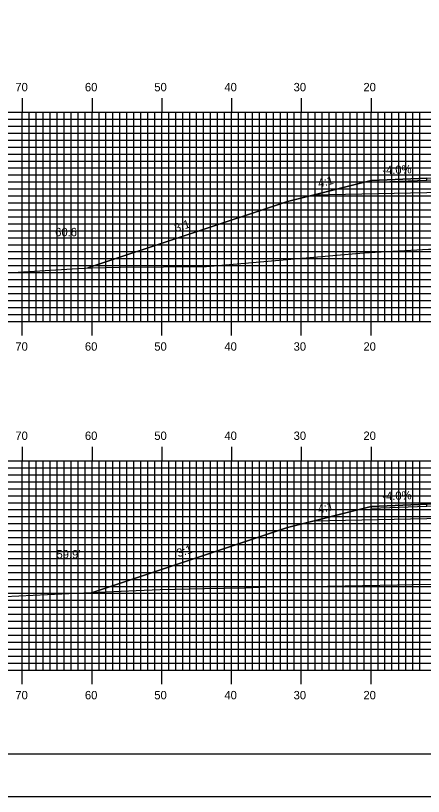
# Model space of a CAD drawing. Extents: x 1788550 to 1788893, y 442591 to 442811.
# Drawn here: x 1788644.7 to 1788703.1, y 442590.5 to 442702.5 of the extents above; entities that cross this region are included whole.
import ezdxf

# ---------------------------------------------------------------- set-up
doc = ezdxf.new("R2010")
doc.units = 0
for name, color, linetype in [('ANNOTATION', 7, 'Continuous'), ('BORDER', 7, 'Continuous'), ('D_Roadway_Centerline', 7, 'Continuous'), ('D_Roadway_Edge_Shoulder', 7, 'Continuous'), ('D_Roadway_SlopeLines', 7, 'Continuous'), ('D_Roadway_SubGrade', 7, 'Continuous'), ('D_Text_Standard', 7, 'Continuous'), ('H_V ANNOTATION', 7, 'Continuous'), ('MAJOR', 7, 'Continuous'), ('MINOR', 7, 'Continuous'), ('PLOT BOUNDARY', 7, 'Continuous'), ('S_Roadway_Centerline', 7, 'Continuous')]:
    doc.layers.add(name, color=color, linetype=linetype)

msp = doc.modelspace()

# ---------------------------------------------------------------- linework, layer by layer
at = {"layer": 'BORDER'}
msp.add_lwpolyline([(1788566.04, 442596.67), (1788886.04, 442596.67), (1788886.04, 442806.67), (1788566.04, 442806.67)], close=True, dxfattribs=at)
at = {"layer": 'D_Roadway_Centerline'}
for points in [[(1788655.04, 442666.34), (1788683.64, 442675.87), (1788687.28, 442676.78), (1788695.64, 442678.87), (1788703.64, 442679.19), (1788715.64, 442679.46), (1788727.64, 442679.72), (1788735.64, 442679.4), (1788744.01, 442677.31), (1788747.64, 442676.4), (1788768.74, 442669.37)], [(1788655.7, 442619.81), (1788683.64, 442629.12), (1788687.28, 442630.03), (1788695.64, 442632.12), (1788703.64, 442632.44), (1788715.64, 442632.71), (1788727.64, 442632.97), (1788735.64, 442632.65), (1788744.01, 442630.56), (1788747.64, 442629.65), (1788766.2, 442623.46)]]:
    msp.add_lwpolyline(points, dxfattribs=at)
at = {"layer": 'D_Roadway_Edge_Shoulder'}
for points in [[(1788703.64, 442679.19), (1788695.64, 442678.87), (1788695.64, 442678.62), (1788703.64, 442678.94)], [(1788703.64, 442632.44), (1788695.64, 442632.12), (1788695.64, 442631.87), (1788703.64, 442632.19)]]:
    msp.add_lwpolyline(points, close=True, dxfattribs=at)
at = {"layer": 'D_Roadway_SlopeLines'}
for points in [[(1788695.64, 442678.87), (1788683.64, 442675.87), (1788655.04, 442666.34)], [(1788695.64, 442632.12), (1788683.64, 442629.12), (1788655.7, 442619.81)]]:
    msp.add_lwpolyline(points, dxfattribs=at)
at = {"layer": 'D_Roadway_SubGrade'}
for points in [[(1788703.64, 442677.11), (1788687.28, 442676.78), (1788695.64, 442678.87), (1788695.64, 442678.62), (1788703.64, 442678.94), (1788715.64, 442679.21), (1788727.64, 442679.47), (1788735.64, 442679.15), (1788735.64, 442679.4), (1788744.01, 442677.31), (1788727.64, 442677.64), (1788715.64, 442677.37)], [(1788703.64, 442630.36), (1788687.28, 442630.03), (1788695.64, 442632.12), (1788695.64, 442631.87), (1788703.64, 442632.19), (1788715.64, 442632.46), (1788727.64, 442632.72), (1788735.64, 442632.4), (1788735.64, 442632.65), (1788744.01, 442630.56), (1788727.64, 442630.89), (1788715.64, 442630.62)]]:
    msp.add_lwpolyline(points, close=True, dxfattribs=at)
at = {"layer": 'MAJOR'}
for p, q in [((1788645.64, 442690.67), (1788645.64, 442688.67)), ((1788655.64, 442690.67), (1788655.64, 442688.67)), ((1788665.64, 442690.67), (1788665.64, 442688.67)), ((1788675.64, 442690.67), (1788675.64, 442688.67)), ((1788685.64, 442690.67), (1788685.64, 442688.67)), ((1788695.64, 442690.67), (1788695.64, 442688.67)), ((1788575.64, 442688.67), (1788855.64, 442688.67)), ((1788575.64, 442688.67), (1788855.64, 442688.67)), ((1788645.64, 442658.67), (1788645.64, 442688.67)), ((1788655.64, 442658.67), (1788655.64, 442688.67)), ((1788665.64, 442658.67), (1788665.64, 442688.67)), ((1788675.64, 442658.67), (1788675.64, 442688.67)), ((1788685.64, 442658.67), (1788685.64, 442688.67)), ((1788695.64, 442658.67), (1788695.64, 442688.67)), ((1788575.64, 442683.67), (1788855.64, 442683.67)), ((1788575.64, 442678.67), (1788855.64, 442678.67)), ((1788575.64, 442673.67), (1788855.64, 442673.67)), ((1788575.64, 442668.67), (1788855.64, 442668.67)), ((1788575.64, 442663.67), (1788855.64, 442663.67)), ((1788575.64, 442658.67), (1788855.64, 442658.67)), ((1788575.64, 442658.67), (1788855.64, 442658.67)), ((1788645.64, 442656.66), (1788645.64, 442658.67)), ((1788655.64, 442656.66), (1788655.64, 442658.67)), ((1788665.64, 442656.66), (1788665.64, 442658.67)), ((1788675.64, 442656.66), (1788675.64, 442658.67)), ((1788685.64, 442656.66), (1788685.64, 442658.67)), ((1788695.64, 442656.66), (1788695.64, 442658.67)), ((1788645.64, 442640.67), (1788645.64, 442638.67)), ((1788655.64, 442640.67), (1788655.64, 442638.67)), ((1788665.64, 442640.67), (1788665.64, 442638.67)), ((1788675.64, 442640.67), (1788675.64, 442638.67)), ((1788685.64, 442640.67), (1788685.64, 442638.67)), ((1788695.64, 442640.67), (1788695.64, 442638.67)), ((1788575.64, 442638.67), (1788855.64, 442638.67)), ((1788575.64, 442638.67), (1788855.64, 442638.67)), ((1788645.64, 442608.67), (1788645.64, 442638.67)), ((1788655.64, 442608.67), (1788655.64, 442638.67)), ((1788665.64, 442608.67), (1788665.64, 442638.67)), ((1788675.64, 442608.67), (1788675.64, 442638.67)), ((1788685.64, 442608.67), (1788685.64, 442638.67)), ((1788695.64, 442608.67), (1788695.64, 442638.67)), ((1788575.64, 442633.67), (1788855.64, 442633.67)), ((1788575.64, 442628.67), (1788855.64, 442628.67)), ((1788575.64, 442623.67), (1788855.64, 442623.67)), ((1788575.64, 442618.67), (1788855.64, 442618.67)), ((1788575.64, 442613.67), (1788855.64, 442613.67)), ((1788575.64, 442608.67), (1788855.64, 442608.67)), ((1788575.64, 442608.67), (1788855.64, 442608.67)), ((1788645.64, 442606.66), (1788645.64, 442608.67)), ((1788655.64, 442606.66), (1788655.64, 442608.67)), ((1788665.64, 442606.66), (1788665.64, 442608.67)), ((1788675.64, 442606.66), (1788675.64, 442608.67)), ((1788685.64, 442606.66), (1788685.64, 442608.67)), ((1788695.64, 442606.66), (1788695.64, 442608.67))]:
    msp.add_line(p, q, dxfattribs=at)
at = {"layer": 'MINOR'}
for p, q in [((1788646.64, 442658.67), (1788646.64, 442688.67)), ((1788647.64, 442658.67), (1788647.64, 442688.67)), ((1788648.64, 442658.67), (1788648.64, 442688.67)), ((1788649.64, 442658.67), (1788649.64, 442688.67)), ((1788650.64, 442658.67), (1788650.64, 442688.67)), ((1788651.64, 442658.67), (1788651.64, 442688.67)), ((1788652.64, 442658.67), (1788652.64, 442688.67)), ((1788653.64, 442658.67), (1788653.64, 442688.67)), ((1788654.64, 442658.67), (1788654.64, 442688.67)), ((1788656.64, 442658.67), (1788656.64, 442688.67)), ((1788657.64, 442658.67), (1788657.64, 442688.67)), ((1788658.64, 442658.67), (1788658.64, 442688.67)), ((1788659.64, 442658.67), (1788659.64, 442688.67)), ((1788660.64, 442658.67), (1788660.64, 442688.67)), ((1788661.64, 442658.67), (1788661.64, 442688.67)), ((1788662.64, 442658.67), (1788662.64, 442688.67)), ((1788663.64, 442658.67), (1788663.64, 442688.67)), ((1788664.64, 442658.67), (1788664.64, 442688.67)), ((1788666.64, 442658.67), (1788666.64, 442688.67)), ((1788667.64, 442658.67), (1788667.64, 442688.67)), ((1788668.64, 442658.67), (1788668.64, 442688.67)), ((1788669.64, 442658.67), (1788669.64, 442688.67)), ((1788670.64, 442658.67), (1788670.64, 442688.67)), ((1788671.64, 442658.67), (1788671.64, 442688.67)), ((1788672.64, 442658.67), (1788672.64, 442688.67)), ((1788673.64, 442658.67), (1788673.64, 442688.67)), ((1788674.64, 442658.67), (1788674.64, 442688.67)), ((1788676.64, 442658.67), (1788676.64, 442688.67)), ((1788677.64, 442658.67), (1788677.64, 442688.67)), ((1788678.64, 442658.67), (1788678.64, 442688.67)), ((1788679.64, 442658.67), (1788679.64, 442688.67)), ((1788680.64, 442658.67), (1788680.64, 442688.67)), ((1788681.64, 442658.67), (1788681.64, 442688.67)), ((1788682.64, 442658.67), (1788682.64, 442688.67)), ((1788683.64, 442658.67), (1788683.64, 442688.67)), ((1788684.64, 442658.67), (1788684.64, 442688.67)), ((1788686.64, 442658.67), (1788686.64, 442688.67)), ((1788687.64, 442658.67), (1788687.64, 442688.67)), ((1788688.64, 442658.67), (1788688.64, 442688.67)), ((1788689.64, 442658.67), (1788689.64, 442688.67)), ((1788690.64, 442658.67), (1788690.64, 442688.67)), ((1788691.64, 442658.67), (1788691.64, 442688.67)), ((1788692.64, 442658.67), (1788692.64, 442688.67)), ((1788693.64, 442658.67), (1788693.64, 442688.67)), ((1788694.64, 442658.67), (1788694.64, 442688.67)), ((1788696.64, 442658.67), (1788696.64, 442688.67)), ((1788697.64, 442658.67), (1788697.64, 442688.67)), ((1788698.64, 442658.67), (1788698.64, 442688.67)), ((1788699.64, 442658.67), (1788699.64, 442688.67)), ((1788700.64, 442658.67), (1788700.64, 442688.67)), ((1788701.64, 442658.67), (1788701.64, 442688.67)), ((1788702.64, 442658.67), (1788702.64, 442688.67)), ((1788575.64, 442687.67), (1788855.64, 442687.67)), ((1788575.64, 442686.67), (1788855.64, 442686.67)), ((1788575.64, 442685.67), (1788855.64, 442685.67)), ((1788575.64, 442684.67), (1788855.64, 442684.67)), ((1788575.64, 442682.67), (1788855.64, 442682.67)), ((1788575.64, 442681.67), (1788855.64, 442681.67)), ((1788575.64, 442680.67), (1788855.64, 442680.67)), ((1788575.64, 442679.67), (1788855.64, 442679.67)), ((1788575.64, 442677.67), (1788855.64, 442677.67)), ((1788575.64, 442676.67), (1788855.64, 442676.67)), ((1788575.64, 442675.67), (1788855.64, 442675.67)), ((1788575.64, 442674.67), (1788855.64, 442674.67)), ((1788575.64, 442672.67), (1788855.64, 442672.67)), ((1788575.64, 442671.67), (1788855.64, 442671.67)), ((1788575.64, 442670.67), (1788855.64, 442670.67)), ((1788575.64, 442669.67), (1788855.64, 442669.67)), ((1788575.64, 442667.67), (1788855.64, 442667.67)), ((1788575.64, 442666.67), (1788855.64, 442666.67)), ((1788575.64, 442665.67), (1788855.64, 442665.67)), ((1788575.64, 442664.67), (1788855.64, 442664.67)), ((1788575.64, 442662.67), (1788855.64, 442662.67)), ((1788575.64, 442661.67), (1788855.64, 442661.67)), ((1788575.64, 442660.67), (1788855.64, 442660.67)), ((1788575.64, 442659.67), (1788855.64, 442659.67)), ((1788646.64, 442608.67), (1788646.64, 442638.67)), ((1788647.64, 442608.67), (1788647.64, 442638.67)), ((1788648.64, 442608.67), (1788648.64, 442638.67)), ((1788649.64, 442608.67), (1788649.64, 442638.67)), ((1788650.64, 442608.67), (1788650.64, 442638.67)), ((1788651.64, 442608.67), (1788651.64, 442638.67)), ((1788652.64, 442608.67), (1788652.64, 442638.67)), ((1788653.64, 442608.67), (1788653.64, 442638.67)), ((1788654.64, 442608.67), (1788654.64, 442638.67)), ((1788656.64, 442608.67), (1788656.64, 442638.67)), ((1788657.64, 442608.67), (1788657.64, 442638.67)), ((1788658.64, 442608.67), (1788658.64, 442638.67)), ((1788659.64, 442608.67), (1788659.64, 442638.67)), ((1788660.64, 442608.67), (1788660.64, 442638.67)), ((1788661.64, 442608.67), (1788661.64, 442638.67)), ((1788662.64, 442608.67), (1788662.64, 442638.67)), ((1788663.64, 442608.67), (1788663.64, 442638.67)), ((1788664.64, 442608.67), (1788664.64, 442638.67)), ((1788666.64, 442608.67), (1788666.64, 442638.67)), ((1788667.64, 442608.67), (1788667.64, 442638.67)), ((1788668.64, 442608.67), (1788668.64, 442638.67)), ((1788669.64, 442608.67), (1788669.64, 442638.67)), ((1788670.64, 442608.67), (1788670.64, 442638.67)), ((1788671.64, 442608.67), (1788671.64, 442638.67)), ((1788672.64, 442608.67), (1788672.64, 442638.67)), ((1788673.64, 442608.67), (1788673.64, 442638.67)), ((1788674.64, 442608.67), (1788674.64, 442638.67)), ((1788676.64, 442608.67), (1788676.64, 442638.67)), ((1788677.64, 442608.67), (1788677.64, 442638.67)), ((1788678.64, 442608.67), (1788678.64, 442638.67)), ((1788679.64, 442608.67), (1788679.64, 442638.67)), ((1788680.64, 442608.67), (1788680.64, 442638.67)), ((1788681.64, 442608.67), (1788681.64, 442638.67)), ((1788682.64, 442608.67), (1788682.64, 442638.67)), ((1788683.64, 442608.67), (1788683.64, 442638.67)), ((1788684.64, 442608.67), (1788684.64, 442638.67)), ((1788686.64, 442608.67), (1788686.64, 442638.67)), ((1788687.64, 442608.67), (1788687.64, 442638.67)), ((1788688.64, 442608.67), (1788688.64, 442638.67)), ((1788689.64, 442608.67), (1788689.64, 442638.67)), ((1788690.64, 442608.67), (1788690.64, 442638.67)), ((1788691.64, 442608.67), (1788691.64, 442638.67)), ((1788692.64, 442608.67), (1788692.64, 442638.67)), ((1788693.64, 442608.67), (1788693.64, 442638.67)), ((1788694.64, 442608.67), (1788694.64, 442638.67)), ((1788696.64, 442608.67), (1788696.64, 442638.67)), ((1788697.64, 442608.67), (1788697.64, 442638.67)), ((1788698.64, 442608.67), (1788698.64, 442638.67)), ((1788699.64, 442608.67), (1788699.64, 442638.67)), ((1788700.64, 442608.67), (1788700.64, 442638.67)), ((1788701.64, 442608.67), (1788701.64, 442638.67)), ((1788702.64, 442608.67), (1788702.64, 442638.67)), ((1788575.64, 442637.67), (1788855.64, 442637.67)), ((1788575.64, 442636.67), (1788855.64, 442636.67)), ((1788575.64, 442635.67), (1788855.64, 442635.67)), ((1788575.64, 442634.67), (1788855.64, 442634.67)), ((1788575.64, 442632.67), (1788855.64, 442632.67)), ((1788575.64, 442631.67), (1788855.64, 442631.67)), ((1788575.64, 442630.67), (1788855.64, 442630.67)), ((1788575.64, 442629.67), (1788855.64, 442629.67)), ((1788575.64, 442627.67), (1788855.64, 442627.67)), ((1788575.64, 442626.67), (1788855.64, 442626.67)), ((1788575.64, 442625.67), (1788855.64, 442625.67)), ((1788575.64, 442624.67), (1788855.64, 442624.67)), ((1788575.64, 442622.67), (1788855.64, 442622.67)), ((1788575.64, 442621.67), (1788855.64, 442621.67)), ((1788575.64, 442620.67), (1788855.64, 442620.67)), ((1788575.64, 442619.67), (1788855.64, 442619.67)), ((1788575.64, 442617.67), (1788855.64, 442617.67)), ((1788575.64, 442616.67), (1788855.64, 442616.67)), ((1788575.64, 442615.67), (1788855.64, 442615.67)), ((1788575.64, 442614.67), (1788855.64, 442614.67)), ((1788575.64, 442612.67), (1788855.64, 442612.67)), ((1788575.64, 442611.67), (1788855.64, 442611.67)), ((1788575.64, 442610.67), (1788855.64, 442610.67)), ((1788575.64, 442609.67), (1788855.64, 442609.67))]:
    msp.add_line(p, q, dxfattribs=at)
at = {"layer": 'PLOT BOUNDARY'}
msp.add_lwpolyline([(1788549.86, 442590.55), (1788889.86, 442590.55), (1788889.86, 442810.55), (1788549.86, 442810.55)], close=True, dxfattribs=at)
at = {"layer": 'S_Roadway_Centerline'}
for points in [[(1788643.53, 442665.63), (1788653.56, 442666.27), (1788655.67, 442666.37), (1788659.7, 442666.44), (1788672.07, 442666.56), (1788694.58, 442668.49), (1788703.86, 442669.02), (1788708.21, 442669.03), (1788724.4, 442670.58), (1788728.18, 442670.65), (1788729.59, 442670.46), (1788740.45, 442668.35), (1788745.46, 442668.18), (1788748.96, 442668.08), (1788761.18, 442668.63), (1788764.27, 442668.92), (1788776.44, 442670.14), (1788784.84, 442670.21)], [(1788643.11, 442619.21), (1788653.38, 442619.7), (1788661.98, 442620.09), (1788665.4, 442620.21), (1788671.77, 442620.36), (1788677.48, 442620.47), (1788680.58, 442620.59), (1788689.42, 442620.71), (1788699.43, 442620.89), (1788701.49, 442620.95), (1788705.39, 442621), (1788713.8, 442621.15), (1788718.27, 442621.22), (1788725.62, 442621.67), (1788736.38, 442621.95), (1788738.22, 442621.99), (1788739.86, 442622.09), (1788762.01, 442623.25), (1788774.75, 442623.9), (1788786.36, 442624.41)]]:
    msp.add_lwpolyline(points, dxfattribs=at)

# ---------------------------------------------------------------- texts
at = {"layer": 'ANNOTATION'}
for s, rotation, p in [('-4.0%', 2.2906, (1788697.28, 442679.74)), ('4:1', 14.0362, (1788688.18, 442677.87)), ('3:1', 18.4348, (1788667.68, 442671.46)), ('-4.0%', 2.2906, (1788697.28, 442632.99)), ('4:1', 14.0362, (1788688.18, 442631.12)), ('3:1', 18.4348, (1788668.01, 442624.82))]:
    msp.add_text(s, height=1.2, rotation=rotation, dxfattribs=at).set_placement(p)
at = {"layer": 'D_Text_Standard'}
for s, p in [("60.6'", (1788650.36, 442670.88)), ("59.9'", (1788650.55, 442624.68))]:
    msp.add_text(s, height=1.2, dxfattribs=at).set_placement(p)
at = {"layer": 'H_V ANNOTATION'}
for s, p in [('70', (1788644.65, 442691.67)), ('60', (1788654.62, 442691.67)), ('50', (1788664.57, 442691.67)), ('40', (1788674.62, 442691.67)), ('30', (1788684.54, 442691.67)), ('20', (1788694.55, 442691.67)), ('70', (1788644.65, 442654.47)), ('60', (1788654.62, 442654.47)), ('50', (1788664.57, 442654.47)), ('40', (1788674.62, 442654.47)), ('30', (1788684.54, 442654.47)), ('20', (1788694.55, 442654.47)), ('70', (1788644.65, 442641.67)), ('60', (1788654.62, 442641.67)), ('50', (1788664.57, 442641.67)), ('40', (1788674.62, 442641.67)), ('30', (1788684.54, 442641.67)), ('20', (1788694.55, 442641.67)), ('70', (1788644.65, 442604.47)), ('60', (1788654.62, 442604.47)), ('50', (1788664.57, 442604.47)), ('40', (1788674.62, 442604.47)), ('30', (1788684.54, 442604.47)), ('20', (1788694.55, 442604.47))]:
    msp.add_text(s, height=1.2, dxfattribs=at).set_placement(p)

doc.saveas('drawing.dxf')
